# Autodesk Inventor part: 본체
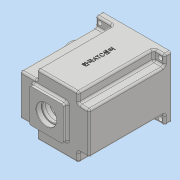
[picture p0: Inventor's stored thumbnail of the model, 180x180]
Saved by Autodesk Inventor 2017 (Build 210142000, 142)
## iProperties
Part Number: 본체
Material: 일반
Document SubType Name: Modeling
Designer: MRC
Density: 1 g/cm^3
Appearance: 기본값
Author: MRC
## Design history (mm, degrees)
sketch "스케치2"
  geometry: L1 (60, 49)-(-50, 49); L2 (-50, 49)-(-50, -49); L3 (-50, -49)-(60, -49); L4 (60, -49)-(60, 49); 2 further points
  constraints: 8 end point, 2 parallel, 1 horizontal, 1 horizontal alignment, 1 midpoint, 1 perpendicular
  dimensions: "d2" = 110 distance of L1.start L1.end; "d3" = 98 distance of L1.end L2.end; "d4" = 50 distance of point (-50, 0) point (0, 0)
extrude "돌출1" new body sketch "스케치2" stored distance "d5" = 130; taper "d6" = 0 deg
sketch "스케치3" dims "d7" = 90
  geometry: L1 (-53, -26)-(-36.729, -26); L2 (-36.729, -26)-(-36.729, 26); L3 (-36.729, 26)-(-53, 26); L4 (-53, 26)-(-53, -26); 3 further points
  constraints: 8 end point, 2 parallel, 1 coincident, 1 horizontal, 1 horizontal alignment, 1 midpoint, 1 perpendicular, 3 other
  dimensions: "d8" = 52 distance of L3.end L1.start; "d9" = 53 distance of point (0, 0) point (-53, 0)
extrude "돌출2" cut sketch "스케치3" distance "d10" = 9; taper "d11" = 0 deg
sketch "스케치4"
  geometry: L1 (-53, 26)-(-36.729, 26) reference; L2 (-53, -26)-(-53, 26) reference; L3 (-36.729, -26)-(-53, -26) reference; L4 (-35.143, -23)-(-50, -23); L5 (-50, -23)-(-50, 23); L6 (-50, 23)-(-35.143, 23); A1 r 45 centre (0, 0) between (-36.729, -26) and (-36.729, 26) reference; A2 r 42 centre (0, 0) between (-35.143, -23) and (-35.143, 23)
  constraints: 6 end point, 2 point on circle, 1 centre point, 3 other
  dimensions: "d12" = 3 radial gap between concentric circles of A1 A2
extrude "돌출3" cut sketch "스케치4" distance "d13" = 112; taper "d14" = 0 deg
sketch "스케치6"
  geometry: C1 r 21 at (-11, 0); C2 r 15 at (20, 0); A1 r 42 centre (0, 0) between (-35.143, -23) and (-35.143, 23) reference
  constraints: 2 centre point, 2 horizontal alignment
  dimensions: "d15" = 42 diameter of C1; "d16" = 11 distance of A1.centre C1.centre; "d17" = 30 diameter of C2; "d18" = 20 distance of A1.centre C2.centre
extrude "돌출4" join sketch "스케치6" distance "d19" = 7; taper "d20" = 0 deg
sketch "스케치8"
  geometry: C1 r 17.5 at (-11, 0); A1 r 21 centre (-11, 0) between (7.984, 8.978) and (7.984, -8.978) reference; 1 further point
  constraints: 1 centre point, 1 coincident
  dimensions: "d23" = 35 diameter of C1
extrude "돌출5" cut sketch "스케치8" distance "d24" = 10; taper "d25" = 0 deg
sketch "스케치9"
  geometry: C1 r 11 at (20, 0); A1 r 15 centre (20, 0) between (7.984, -8.978) and (7.984, 8.978) reference; 1 further point
  constraints: 1 centre point, 1 coincident
  dimensions: "d26" = 22 diameter of C1
extrude "돌출6" cut sketch "스케치9" distance "d27" = 7; taper "d28" = 0 deg
sketch "스케치10"
  geometry: C1 r 11 at (0, 0) reference; C2 r 9.5 at (0, 0); 1 further point
  constraints: 1 centre point, 1 coincident
  dimensions: "d29" = 19 diameter of C2
extrude "돌출7" cut sketch "스케치10" distance "d30" = 3; taper "d31" = 0 deg
sketch "스케치11"
  geometry: C1 r 17.5 at (0, 0) reference; C2 r 14 at (0, 0); 1 further point
  constraints: 1 centre point, 1 coincident
  dimensions: "d32" = 28 diameter of C2
extrude "돌출8" cut sketch "스케치11" stored distance "d33" = 3; taper "d34" = 0 deg
sketch "스케치12"
  geometry: L1 (-38, -27)-(16, -27); L2 (16, -27)-(16, 27); L3 (16, 27)-(-38, 27); L4 (-38, 27)-(-38, -27); L5 (-38, -27)-(16, 27); L6 (16, -27)-(-38, 27); C1 r 14 at (-11, 0) reference; 1 further point
  constraints: 12 end point, 2 midpoint, 2 parallel, 1 horizontal, 1 perpendicular
  dimensions: "d35" = 54 distance of L3.end L2.end; "d36" = 54 distance of L2.end L1.end
extrude "돌출9" join sketch "스케치12" distance "d37" = 7; taper "d38" = 0 deg
sketch "스케치13"
  geometry: C1 r 14 at (-11, 0) reference; C2 r 16 at (-11, 0); 1 further point
  constraints: 1 centre point, 1 coincident
  dimensions: "d39" = 32 diameter of C2
extrude "돌출10" cut sketch "스케치13" distance "d40" = 8.3; taper "d41" = 0 deg
chamfer "모따기1" distance "d42" = 0.8; stored, may be unused: second distance "d43" = 2, angle "d44" = 30 deg
fillet "모깎기1" dims "d45" = 0.3
chamfer "모따기2" distance "d46" = 1; stored, may be unused: second distance "d47" = 2, angle "d48" = 30 deg
fillet "모깎기2" dims "d49" = 3
sketch "스케치14"
  geometry: L1 (-4, 36)-(-4, 41.809); L2 (4, 36)-(4, 41.809); A1 r 42 centre (0, 0) between (-35.143, -23) and (-35.143, 23) reference; A2 r 45 centre (0, 0) between (-36.729, -26) and (-36.729, 26) reference; A3 r 4 centre (0, 36) between (-4, 36) and (4, 36); A4 r 42 centre (0, 0) between (4, 41.809) and (-4, 41.809)
  constraints: 6 point on circle, 4 end point, 2 centre point, 2 tangent, 2 vertical, 1 coincident, 1 vertical alignment
  dimensions: "d50" = 8 diameter of A3; "d51" = 36 distance of A3.centre A1.centre
extrude "돌출11" join sketch "스케치14" stored distance "d52" = 8.3; taper "d53" = 0 deg
hole "구멍1" diameter "d56" = 3.242; stored, may be unused: countersink angle "d60" = 90 deg, drill point angle "d62" = 118 deg; dims "d54" = 10, "d55" = 10, "d57" = 7, "d58" = 4, "d59" = 2, "d61" = 9
sketch "스케치15"
  geometry: L1 (-60, -49)-(-33, -49); L2 (-33, -49)-(-33, -33); L3 (-33, -33)-(-60, -33); L4 (-60, -33)-(-60, -49); L5 (50, -49)-(33, -49); L6 (33, -49)-(33, -33); L7 (33, -33)-(50, -33); L8 (50, -33)-(50, -49); 1 further point
  constraints: 16 end point, 4 parallel, 2 horizontal, 2 perpendicular
  dimensions: "d63" = 27 distance of L3.end L2.end; "d64" = 16 distance of L2.end L1.end; "d65" = 17 distance of L6.end L7.end; "d66" = 16 distance of L5.end L6.end
extrude "돌출12" cut sketch "스케치15" distance "d67" = 120; taper "d68" = 0 deg
sketch "스케치16"
  geometry: L1 (0, 0)-(98, 0) reference; C1 r 15 at (49, -89); C2 r 22.5 at (49, -40); 1 further point
  constraints: 2 centre point, 2 vertical alignment
  dimensions: "d69" = 30 diameter of C1; "d70" = 45 diameter of C2; "d71" = 40 distance from line of C2.centre L1; "d72" = 49 distance of C1.centre C2.centre
extrude "돌출13" join sketch "스케치16" distance "d73" = 5; taper "d74" = 0 deg
extrude "돌출14" join sketch "스케치16" distance "d75" = 10; taper "d76" = 0 deg
hole "구멍2" diameter "d79" = 33.376; stored, may be unused: countersink angle "d83" = 90 deg, drill point angle "d85" = 118 deg; dims "d77" = 10, "d78" = 10, "d80" = 70, "d81" = 4, "d82" = 2, "d84" = 77.3
hole "구멍3" diameter "d88" = 20; stored, may be unused: countersink angle "d92" = 90 deg, drill point angle "d94" = 118 deg; dims "d86" = 10, "d87" = 10, "d89" = 70, "d90" = 30, "d91" = 5, "d93" = 77.3
sketch "스케치17"
  geometry: L1 (50, 49)-(-60, 49) reference; L2 (-60, 49)-(-60, -49) reference; C1 r 3.5 at (-53, 42); C2 r 3.5 at (43, 42)
  constraints: 2 centre point, 1 horizontal alignment
  dimensions: "d95" = 7 diameter of C1; "d96" = 7 diameter of C2; "d97" = 96 distance of C2.centre C1.centre; "d98" = 7 distance from line of L2 C1.centre; "d99" = 7 distance from line of L1 C1.centre
extrude "돌출15" cut sketch "스케치17" distance "d100" = 10; taper "d101" = 0 deg
fillet "모깎기3" dims "d102" = 6
fillet "모깎기4" dims "d103" = 3
fillet "모깎기5" dims "d104" = 3
fillet "모깎기6" dims "d105" = 3
fillet "모깎기7" dims "d106" = 3
fillet "모깎기8" dims "d107" = 3
fillet "모깎기9" dims "d108" = 3
fillet "모깎기10" dims "d109" = 3
fillet "모깎기11" dims "d110" = 3
fillet "모깎기12" dims "d111" = 3
fillet "모깎기13" dims "d112" = 3
fillet "모깎기14" dims "d113" = 3
fillet "모깎기15" dims "d114" = 3
fillet "모깎기16" dims "d115" = 6
chamfer "모따기3" distance "d116" = 1; stored, may be unused: second distance "d117" = 2, angle "d118" = 30 deg
fillet "모깎기17" dims "d119" = 3
fillet "모깎기18" dims "d120" = 3
fillet "모깎기19" dims "d121" = 3
fillet "모깎기20" dims "d122" = 3
fillet "모깎기21" dims "d123" = 0.3
sketch "스케치19"
  geometry: L1 (0, -130)-(21, -130) reference; 2 further points
  constraints: 1 coincident, 1 other
feature "엠보싱1" sketch "스케치19" dims "d125" = 0.5, "d126" = 0
chamfer "모따기4" distance "d127" = 1; stored, may be unused: second distance "d128" = 2, angle "d129" = 30 deg
node "솔리드1"
mirror "미러1"
mirror "미러2"
mirror "미러3"
